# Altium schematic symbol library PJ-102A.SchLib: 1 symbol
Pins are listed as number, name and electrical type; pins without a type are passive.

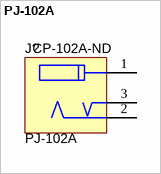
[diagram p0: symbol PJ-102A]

## PJ-102A
designator J?  Supplier Part Number: CP-102A-ND
CONN JACK POWER 2.1MM PCB; Manufacturer: CUI Inc; SymbolCreator: a0799628; CompType: Power Jack; U/M: EA; Current Rating: 2.5A; Plug/Mating Plug Diameter: 2.1mm ID, 5.5mm OD; Gender: Male; Number of Positions/Contacts: 2 Conductors, 3 Contacts; Shielding: Unshielded; Internal Switch(s): Single Switch, Normally Closed; VDC_V: 16VDC
footprint PJ-102A (CU INC PJ-102A)
pins: 1, 2, 3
